// Mitsubishi GX Works2 project: 700-FX参考例程   PLC: FX1S

PROGRAM MAIN
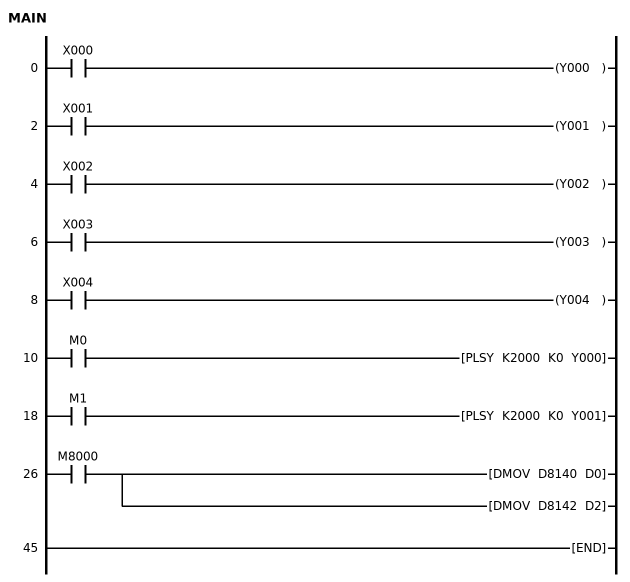
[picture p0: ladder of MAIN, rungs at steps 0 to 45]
0     LD      X000
      OUT     Y000
2     LD      X001
      OUT     Y001
4     LD      X002
      OUT     Y002
6     LD      X003
      OUT     Y003
8     LD      X004
      OUT     Y004
10    LD      M0
      PLSY    K2000 K0 Y000
18    LD      M1
      PLSY    K2000 K0 Y001
26    LD      M8000
      DMOV    D8140 D0
      DMOV    D8142 D2
45    END
END_PROGRAM
